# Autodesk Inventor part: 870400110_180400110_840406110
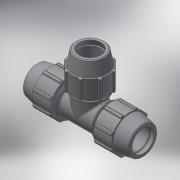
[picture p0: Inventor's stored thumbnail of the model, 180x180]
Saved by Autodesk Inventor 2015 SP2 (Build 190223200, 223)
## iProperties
Created: 2017-02
Part Number: 870400110_180400110_840406110
Material: Generic
Description: PLASSON TEE 110-110-110
Document SubType Name: Modeling
Designer: KIM
Mass: 2642.84 g
Surface Area: 3396.39 cm^2
Volume: 2642.84 cm^3
Density: 1 g/cm^3
Appearance: Default
Author: KIM
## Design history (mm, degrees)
derived "87040.ipt"
feature "Solid1::87040.ipt"
tag "TaggingFeature1"
body "Solid1"
other parameters: "d4" = 24.5, "d5" = 73.5, "d7" = 181, "d13" = 120 deg, "d14" = 143, "d15" = 8 deg, "d18" = 5.5, "d19" = 35 deg, "d20" = 17.5 deg, "d21" = 168.33, "d23" = 0, "d25" = 360 deg, "d27" = 3.62, "d42" = 102.9, "d43" = 5.43, "d46" = 3.3, "d63" = 196, "d67" = 135.75, "d77" = 181, "d78" = 8 deg, "d79" = 294, "d80" = 120 deg, "d81" = 143, "d82" = 24.5, "d85" = 135.75, "d87" = 9.8, "d88" = 9.8, "d89" = 73.5, "d90" = 102.9, "d98" = 168.33, "d99" = 35 deg, "d100" = 17.5 deg, "d102" = 0, "d103" = 3.62, "d107" = 360 deg, "d109" = 3.3, "d112" = 5.5, "d118" = 360 deg, "d121" = 0, "d128" = 583, "d131" = 99, "d132" = 99, "d133" = 196, "d134" = 3.92, "d152" = 0, "d154" = 0, "d156" = 0, "d158" = 0, "d163" = 16.33333, "d165" = 19.6, "d166" = 128.9625, "d167" = 128.9625, "d168" = 3.92, "d169" = 149.325, "d170" = 1.96, "d171" = 6.86, "d172" = 142.5375, "d173" = 4.9, "d174" = 4.08333, "d175" = 3.675, "d176" = 2.2, "d177" = 5.5, "E_" = 181, "A_" = 294, "l_" = 196, "H_" = 583, "d162" = 19.6, "d164" = 23.52
